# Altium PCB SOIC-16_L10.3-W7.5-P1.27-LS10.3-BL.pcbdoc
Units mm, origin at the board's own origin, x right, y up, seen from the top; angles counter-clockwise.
Board outline 23.26 x 24.6 mm, 2 copper layers (Top Layer, Bottom Layer), stack 0 mm thick; 1 components, 0 nets, 16 pads, 0 vias.
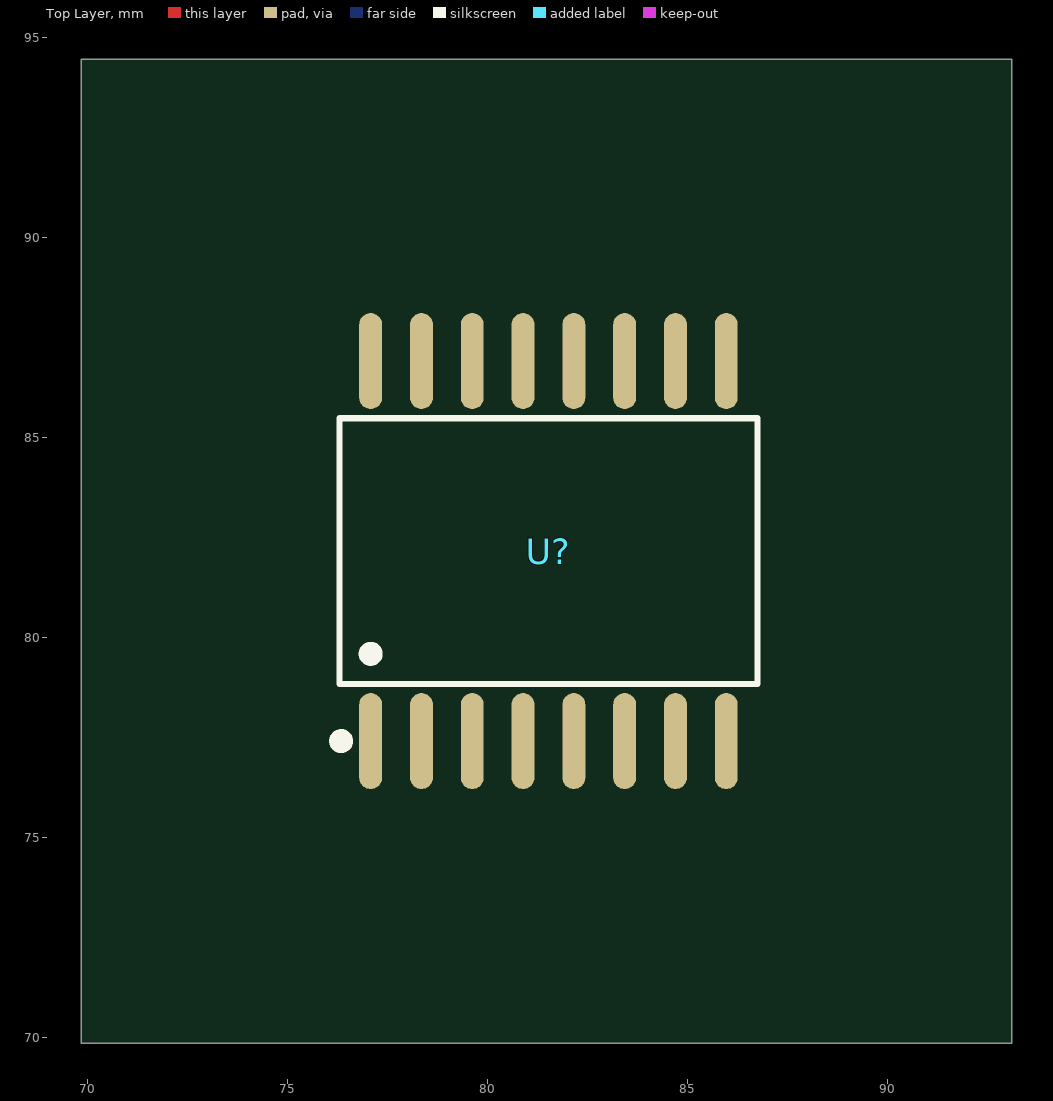
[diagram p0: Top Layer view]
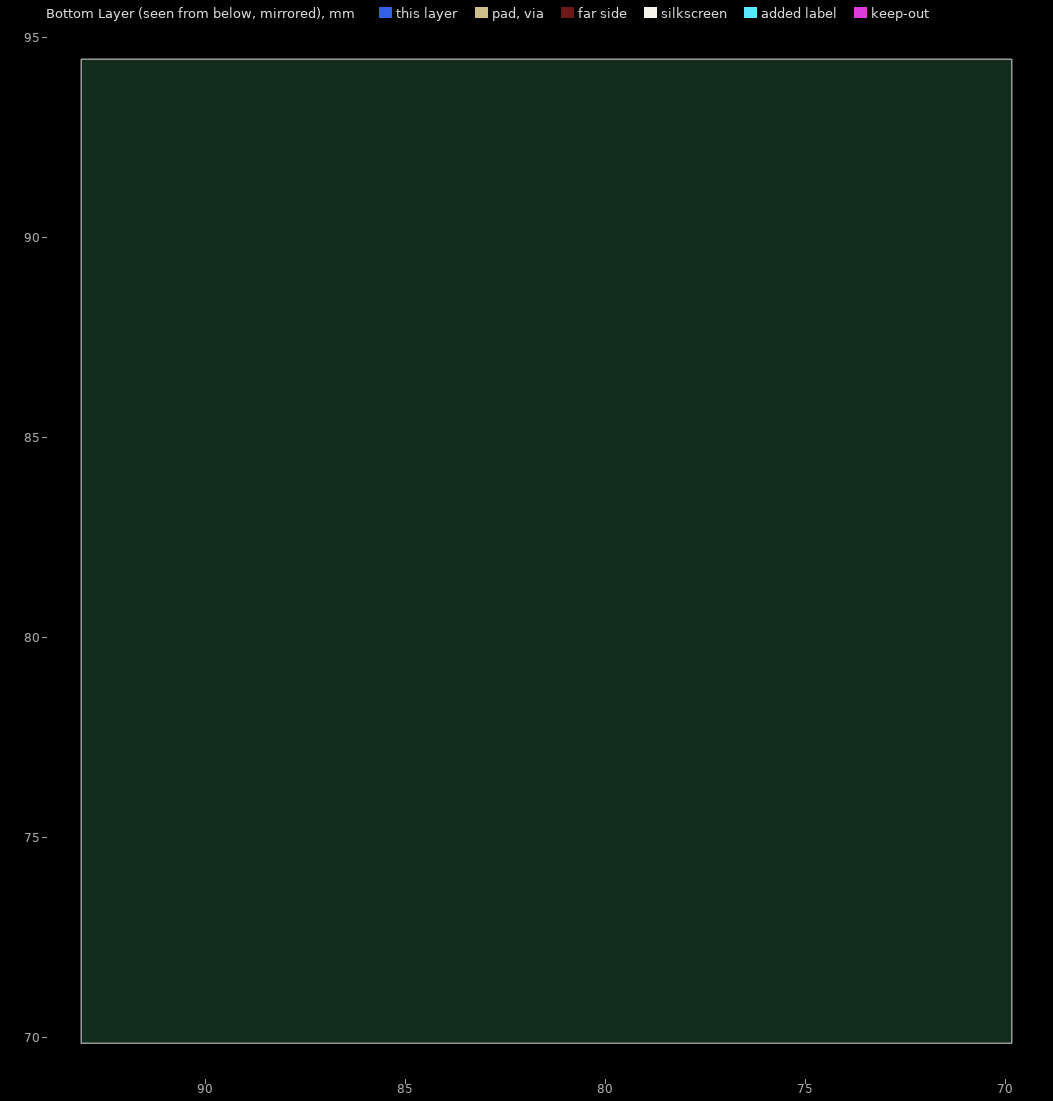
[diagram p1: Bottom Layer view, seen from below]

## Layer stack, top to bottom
Top Layer: signal copper (thickness not stored)
Bottom Layer: signal copper (thickness not stored)

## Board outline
93.111,69.85 69.85,69.85 69.85,94.451 93.111,94.451

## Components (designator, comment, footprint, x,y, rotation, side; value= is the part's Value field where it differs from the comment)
U? "" SOIC-16_L10.3-W7.5-P1.27-LS10.3-BL 81.535,82.151 r0 top

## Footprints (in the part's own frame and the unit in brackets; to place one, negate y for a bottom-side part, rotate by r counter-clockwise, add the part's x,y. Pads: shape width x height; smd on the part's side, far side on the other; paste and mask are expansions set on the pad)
SOIC-16_L10.3-W7.5-P1.27-LS10.3-BL [mm]
  oval 0.574x2.401 smd: 1(-4.445,-4.75) 2(-3.175,-4.75) 3(-1.905,-4.75) 4(-0.635,-4.75) 5(0.635,-4.75) 6(1.905,-4.75) 7(3.175,-4.75) 8(4.445,-4.75) 9(4.445,4.75) 10(3.175,4.75) 11(1.905,4.75) 12(0.635,4.75) 13(-0.635,4.75) 14(-1.905,4.75) 15(-3.175,4.75) 16(-4.445,4.75)
  silkscreen extent -5.33,-4.9 5.23,3.32

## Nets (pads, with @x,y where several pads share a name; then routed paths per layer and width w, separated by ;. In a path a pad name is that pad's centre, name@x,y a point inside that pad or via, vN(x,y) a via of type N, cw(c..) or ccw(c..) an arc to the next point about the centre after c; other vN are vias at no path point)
pads on no net: U?.1 U?.2 U?.3 U?.4 U?.5 U?.6 U?.7 U?.8 U?.9 U?.10 U?.11 U?.12 U?.13 U?.14 U?.15 U?.16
